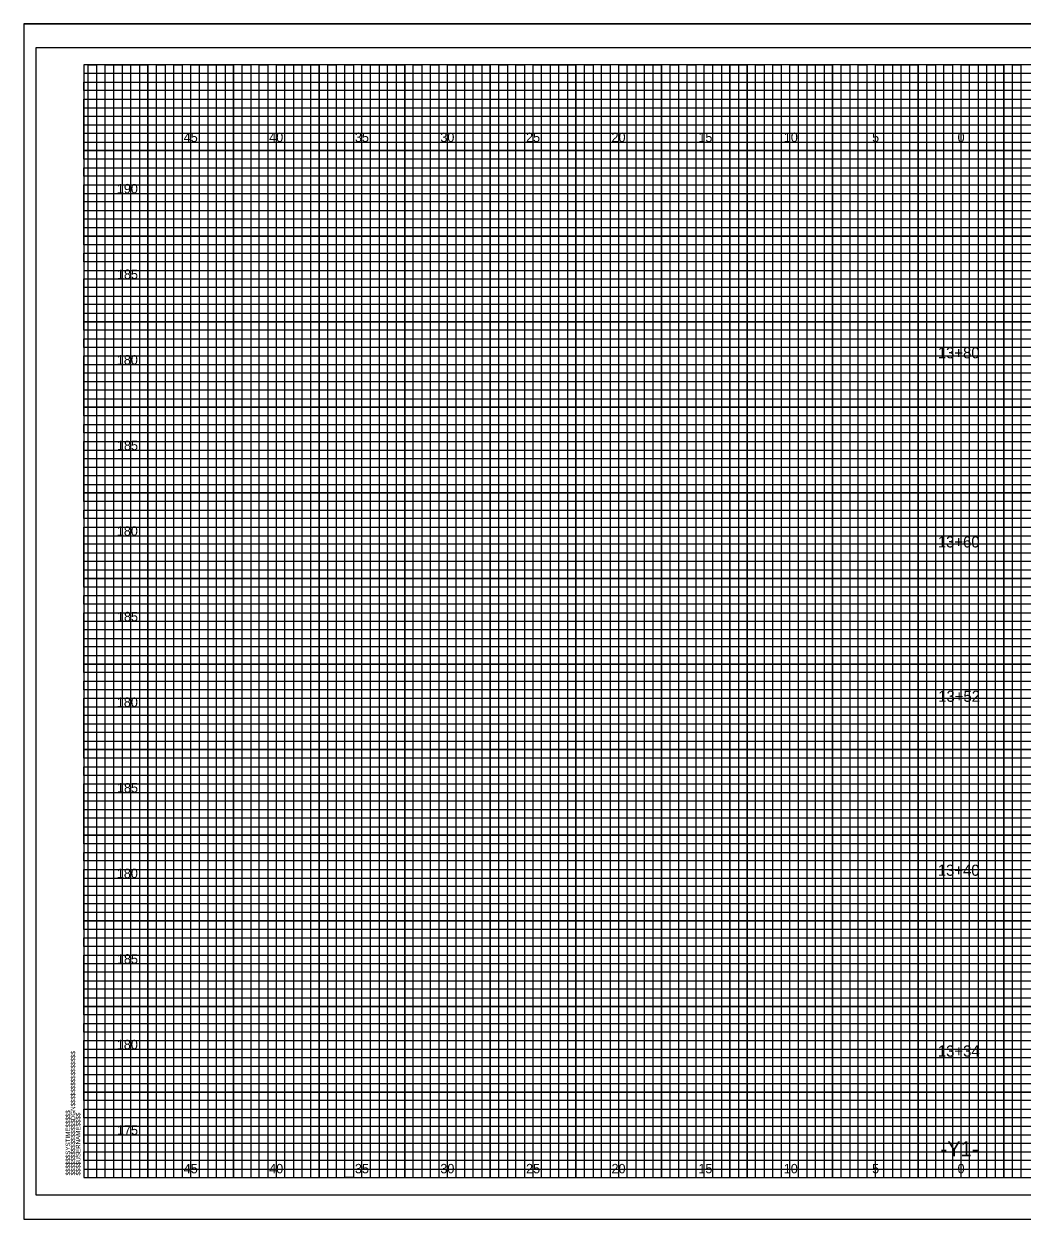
# Model space of a CAD drawing. Extents: x -4 to 103, y -2 to 209.
# Drawn here: x -3.5 to 54.8, y 139.2 to 209.1 of the extents above; entities that cross this region are included whole.
import ezdxf

# ---------------------------------------------------------------- set-up
doc = ezdxf.new("R2010")
doc.units = 0
for name, color, linetype in [('Old_Level_10', 7, 'Continuous'), ('Old_Level_16', 7, 'Continuous'), ('Old_Level_3', 7, 'Continuous'), ('Old_Level_4', 7, 'Continuous'), ('Old_Level_5', 7, 'Continuous'), ('Old_Level_6', 7, 'Continuous'), ('Old_Level_8', 7, 'Continuous'), ('Prop Dimension', 7, 'Continuous'), ('Prop XS Dump Level', 7, 'Continuous'), ('Prop XS Finish Grade Pavement', 7, 'Continuous'), ('Prop XS Subgrade Earthwork', 7, 'Continuous')]:
    doc.layers.add(name, color=color, linetype=linetype)

msp = doc.modelspace()

# ---------------------------------------------------------------- linework, layer by layer
at = {"layer": 'Old_Level_10'}
for p, q in [((1.25, 141.65), (1.25, 206.65)), ((3.75, 141.65), (3.75, 206.65)), ((6.25, 141.65), (6.25, 206.65)), ((8.75, 141.65), (8.75, 206.65)), ((11.25, 141.65), (11.25, 206.65)), ((13.75, 141.65), (13.75, 206.65)), ((16.25, 141.65), (16.25, 206.65)), ((18.75, 141.65), (18.75, 206.65)), ((21.25, 141.65), (21.25, 206.65)), ((23.75, 141.65), (23.75, 206.65)), ((26.25, 141.65), (26.25, 206.65)), ((28.75, 141.65), (28.75, 206.65)), ((31.25, 141.65), (31.25, 206.65)), ((33.75, 141.65), (33.75, 206.65)), ((36.25, 141.65), (36.25, 206.65)), ((38.75, 141.65), (38.75, 206.65)), ((41.25, 141.65), (41.25, 206.65)), ((43.75, 141.65), (43.75, 206.65)), ((46.25, 141.65), (46.25, 206.65)), ((48.75, 141.65), (48.75, 206.65)), ((51.25, 141.65), (51.25, 206.65)), ((53.75, 141.65), (53.75, 206.65)), ((0, 204.15), (74.25, 204.15)), ((0, 201.65), (102.5, 201.65)), ((0, 199.15), (102.5, 199.15)), ((0, 196.65), (102.5, 196.65)), ((0, 194.15), (102.5, 194.15)), ((0, 191.65), (102.5, 191.65)), ((0, 189.15), (102.5, 189.15)), ((0, 186.65), (102.5, 186.65)), ((0, 184.15), (102.5, 184.15)), ((0, 181.65), (102.5, 181.65)), ((0, 179.15), (102.5, 179.15)), ((0, 176.65), (102.5, 176.65)), ((0, 174.15), (102.5, 174.15)), ((0, 171.65), (102.5, 171.65)), ((0, 169.15), (102.5, 169.15)), ((0, 166.65), (102.5, 166.65)), ((0, 164.15), (102.5, 164.15)), ((0, 161.65), (102.5, 161.65)), ((0, 159.15), (102.5, 159.15)), ((0, 156.65), (102.5, 156.65)), ((0, 154.15), (102.5, 154.15)), ((0, 151.65), (102.5, 151.65)), ((0, 149.15), (102.5, 149.15)), ((0, 146.65), (102.5, 146.65)), ((0, 144.15), (102.5, 144.15))]:
    msp.add_line(p, q, dxfattribs=at)
at = {"layer": 'Old_Level_3'}
for p, q in [((-3.5, 209.05), (103.4, 209.05)), ((-3.5, 209.05), (-3.5, 139.225)), ((-3.5, 139.225), (103.4, 139.225))]:
    msp.add_line(p, q, dxfattribs=at)
at = {"layer": 'Old_Level_4'}
msp.add_lwpolyline([(103, 207.65), (-2.8, 207.65), (-2.8, 140.65), (103, 140.65)], close=True, dxfattribs=at)
at = {"layer": 'Old_Level_5'}
msp.add_lwpolyline([(103.4, 209.05), (-3.5, 209.05), (-3.5, 139.225), (103.4, 139.225)], close=True, dxfattribs=at)
at = {"layer": 'Old_Level_6'}
msp.add_lwpolyline([(102.5, 206.65), (0, 206.65), (0, 141.65), (102.5, 141.65)], close=True, dxfattribs=at)
at = {"layer": 'Old_Level_8'}
for points in [[(1.25, 141.65), (1.25, 206.65), (3.75, 206.65), (3.75, 141.65), (6.25, 141.65), (6.25, 206.65), (8.75, 206.65), (8.75, 141.65), (11.25, 141.65), (11.25, 206.65), (13.75, 206.65), (13.75, 141.65), (16.25, 141.65), (16.25, 206.65), (18.75, 206.65), (18.75, 141.65), (21.25, 141.65), (21.25, 206.65), (23.75, 206.65), (23.75, 141.65), (26.25, 141.65), (26.25, 206.65), (28.75, 206.65), (28.75, 141.65), (31.25, 141.65), (31.25, 206.65), (33.75, 206.65), (33.75, 141.65), (36.25, 141.65), (36.25, 206.65), (38.75, 206.65), (38.75, 141.65), (41.25, 141.65), (41.25, 206.65), (43.75, 206.65), (43.75, 141.65), (46.25, 141.65), (46.25, 206.65), (48.75, 206.65), (48.75, 141.65), (51.25, 141.65), (51.25, 206.65), (53.75, 206.65), (53.75, 141.65)], [(102.5, 201.65), (0, 201.65), (0, 204.15), (74.25, 204.15)], [(102.5, 196.65), (0, 196.65), (0, 199.15), (102.5, 199.15)], [(102.5, 191.65), (0, 191.65), (0, 194.15), (102.5, 194.15)], [(102.5, 186.65), (0, 186.65), (0, 189.15), (102.5, 189.15)], [(102.5, 181.65), (0, 181.65), (0, 184.15), (102.5, 184.15)], [(102.5, 176.65), (0, 176.65), (0, 179.15), (102.5, 179.15)], [(102.5, 171.65), (0, 171.65), (0, 174.15), (102.5, 174.15)], [(102.5, 166.65), (0, 166.65), (0, 169.15), (102.5, 169.15)], [(102.5, 161.65), (0, 161.65), (0, 164.15), (102.5, 164.15)], [(102.5, 156.65), (0, 156.65), (0, 159.15), (102.5, 159.15)], [(102.5, 151.65), (0, 151.65), (0, 154.15), (102.5, 154.15)], [(102.5, 146.65), (0, 146.65), (0, 149.15), (102.5, 149.15)], [(0, 144.15), (102.5, 144.15)]]:
    msp.add_lwpolyline(points, dxfattribs=at)
at = {"layer": 'Prop Dimension'}
for points in [[(0, 203.65), (0, 204.65), (74.25, 204.65), (74.25, 205.15), (0, 205.15), (0, 205.65), (74.25, 205.65), (74.25, 206.15), (0, 206.15)], [(0.25, 141.65), (0.25, 206.65), (0.75, 206.65), (0.75, 141.65), (1.75, 141.65), (1.75, 206.65), (2.25, 206.65), (2.25, 141.65), (2.75, 141.65), (2.75, 206.65), (3.25, 206.65), (3.25, 141.65), (4.25, 141.65), (4.25, 206.65), (4.75, 206.65), (4.75, 141.65), (5.25, 141.65), (5.25, 206.65), (5.75, 206.65), (5.75, 141.65), (6.75, 141.65), (6.75, 206.65), (7.25, 206.65), (7.25, 141.65), (7.75, 141.65), (7.75, 206.65), (8.25, 206.65), (8.25, 141.65), (9.25, 141.65), (9.25, 206.65), (9.75, 206.65), (9.75, 141.65), (10.25, 141.65), (10.25, 206.65), (10.75, 206.65), (10.75, 141.65), (11.75, 141.65), (11.75, 206.65), (12.25, 206.65), (12.25, 141.65), (12.75, 141.65), (12.75, 206.65), (13.25, 206.65), (13.25, 141.65), (14.25, 141.65), (14.25, 206.65), (14.75, 206.65), (14.75, 141.65), (15.75, 141.65), (15.25, 141.65), (15.25, 206.65), (15.75, 206.65), (15.75, 141.65), (16.75, 141.65), (16.75, 206.65), (17.25, 206.65), (17.25, 141.65), (17.75, 141.65), (17.75, 206.65), (18.25, 206.65), (18.25, 141.65), (19.25, 141.65), (19.25, 206.65), (19.75, 206.65), (19.75, 141.65), (20.25, 141.65), (20.25, 206.65), (20.75, 206.65), (20.75, 141.65), (21.75, 141.65), (21.75, 206.65), (22.25, 206.65), (22.25, 141.65), (22.75, 141.65), (22.75, 206.65), (23.25, 206.65), (23.25, 141.65), (24.25, 141.65), (24.25, 206.65), (24.75, 206.65), (24.75, 141.65), (25.25, 141.65), (25.25, 206.65), (25.75, 206.65), (25.75, 141.65), (26.75, 141.65), (26.75, 206.65), (27.25, 206.65), (27.25, 141.65), (27.75, 141.65), (27.75, 206.65), (28.25, 206.65), (28.25, 141.65), (29.25, 141.65), (29.25, 206.65), (29.75, 206.65), (29.75, 141.65), (30.25, 141.65), (30.25, 206.65), (30.75, 206.65), (30.75, 141.65)], [(30.75, 141.65), (31.75, 141.65), (31.75, 206.65), (32.25, 206.65), (32.25, 141.65), (32.75, 141.65), (32.75, 206.65), (33.25, 206.65), (33.25, 141.65), (34.25, 141.65), (34.25, 206.65), (34.75, 206.65), (34.75, 141.65), (35.25, 141.65), (35.25, 206.65), (35.75, 206.65), (35.75, 141.65), (36.75, 141.65), (36.75, 206.65), (37.25, 206.65), (37.25, 141.65), (37.75, 141.65), (37.75, 206.65), (37.75, 141.65)], [(38.25, 206.65), (38.25, 141.65), (39.25, 141.65), (39.25, 206.65), (39.75, 206.65), (39.75, 141.65), (40.25, 141.65), (40.25, 206.65), (40.75, 206.65), (40.75, 141.65), (41.75, 141.65), (41.75, 206.65), (42.25, 206.65), (42.25, 141.65), (42.75, 141.65), (42.75, 206.65), (43.25, 206.65), (43.25, 141.65), (43.75, 141.65), (44.25, 141.65), (44.25, 206.65), (44.75, 206.65), (44.75, 141.65), (45.25, 141.65), (45.25, 206.65), (45.75, 206.65), (45.75, 141.65), (46.75, 141.65), (46.75, 206.65), (47.25, 206.65), (47.25, 141.65), (47.75, 141.65), (47.75, 206.65), (48.25, 206.65), (48.25, 141.65), (49.25, 141.65), (49.25, 206.65), (49.75, 206.65), (49.75, 141.65), (50.25, 141.65), (50.25, 206.65), (50.75, 206.65), (50.75, 141.65), (51.75, 141.65), (51.75, 206.65), (52.25, 206.65), (52.25, 141.65), (52.75, 141.65), (52.75, 206.65), (53.25, 206.65), (53.25, 141.65), (54.25, 141.65), (54.25, 206.65), (54.75, 206.65), (54.75, 141.65), (55.25, 141.65)], [(102.5, 203.65), (0, 203.65)], [(102.5, 202.65), (0, 202.65), (0, 203.15), (102.5, 203.15)], [(102.5, 201.15), (0, 201.15), (0, 202.15), (102.5, 202.15)], [(102.5, 200.15), (0, 200.15), (0, 200.65), (102.5, 200.65)], [(102.5, 198.65), (0, 198.65), (0, 199.65), (102.5, 199.65)], [(102.5, 197.65), (0, 197.65), (0, 198.15), (102.5, 198.15)], [(102.5, 196.15), (0, 196.15), (0, 197.15), (102.5, 197.15)], [(102.5, 195.15), (0, 195.15), (0, 195.65), (102.5, 195.65)], [(0, 194.65), (102.5, 194.65)], [(102.5, 193.65), (0, 193.65)], [(102.5, 192.65), (0, 192.65), (0, 193.15), (102.5, 193.15)], [(102.5, 191.15), (0, 191.15), (0, 192.15), (102.5, 192.15)], [(102.5, 190.15), (0, 190.15), (0, 190.65), (102.5, 190.65)], [(102.5, 188.65), (0, 188.65), (0, 189.65), (102.5, 189.65)], [(102.5, 187.65), (0, 187.65), (0, 188.15), (102.5, 188.15)], [(102.5, 186.15), (0, 186.15), (0, 187.15), (102.5, 187.15)], [(102.5, 185.15), (0, 185.15), (0, 185.65), (102.5, 185.65)], [(102.5, 183.65), (0, 183.65), (0, 184.65), (102.5, 184.65)], [(102.5, 182.65), (0, 182.65), (0, 183.15), (102.5, 183.15)], [(102.5, 181.15), (0, 181.15), (0, 182.15), (102.5, 182.15)], [(102.5, 180.15), (0, 180.15), (0, 180.65), (102.5, 180.65)], [(102.5, 178.65), (0, 178.65), (0, 179.65), (102.5, 179.65)], [(102.5, 177.65), (0, 177.65), (0, 178.15), (102.5, 178.15)], [(102.5, 176.15), (0, 176.15), (0, 177.15), (102.5, 177.15)], [(102.5, 175.15), (0, 175.15), (0, 175.65), (102.5, 175.65)], [(102.5, 173.65), (0, 173.65), (0, 174.65), (102.5, 174.65)], [(102.5, 172.65), (0, 172.65), (0, 173.15)], [(0, 173.15), (102.5, 173.15)], [(102.5, 171.15), (0, 171.15), (0, 172.15), (102.5, 172.15)], [(102.5, 170.15), (0, 170.15), (0, 170.65), (102.5, 170.65)], [(102.5, 168.65), (0, 168.65), (0, 169.65), (102.5, 169.65)], [(102.5, 167.65), (0, 167.65), (0, 168.15), (102.5, 168.15)], [(102.5, 166.15), (0, 166.15), (0, 167.15), (102.5, 167.15)], [(102.5, 165.15), (0, 165.15), (0, 165.65), (102.5, 165.65)], [(102.5, 163.65), (0, 163.65), (0, 164.65), (102.5, 164.65)], [(102.5, 162.65), (0, 162.65), (0, 163.15), (102.5, 163.15)], [(102.5, 161.15), (0, 161.15), (0, 162.15), (102.5, 162.15)], [(102.5, 160.15), (0, 160.15), (0, 160.65), (102.5, 160.65)], [(102.5, 158.65), (0, 158.65), (0, 159.65), (102.5, 159.65)], [(102.5, 157.65), (0, 157.65), (0, 158.15), (102.5, 158.15)], [(102.5, 156.15), (0, 156.15), (0, 157.15), (102.5, 157.15)], [(102.5, 155.15), (0, 155.15), (0, 155.65), (102.5, 155.65)], [(102.5, 153.65), (0, 153.65), (0, 154.65), (102.5, 154.65)], [(102.5, 152.65), (0, 152.65), (0, 153.15), (102.5, 153.15)], [(102.5, 151.15), (0, 151.15), (0, 152.15), (102.5, 152.15)], [(102.5, 150.15), (0, 150.15), (0, 150.65), (102.5, 150.65)], [(102.5, 148.65), (0, 148.65), (0, 149.65), (102.5, 149.65)], [(102.5, 147.65), (0, 147.65), (0, 148.15), (102.5, 148.15)], [(102.5, 146.15), (0, 146.15), (0, 147.15), (102.5, 147.15)], [(102.5, 145.15), (0, 145.15), (0, 145.65), (102.5, 145.65)], [(102.5, 143.65), (0, 143.65), (0, 144.65), (102.5, 144.65)], [(102.5, 142.65), (0, 142.65), (0, 143.15), (102.5, 143.15)], [(0, 142.15), (102.5, 142.15)]]:
    msp.add_lwpolyline(points, dxfattribs=at)

# ---------------------------------------------------------------- texts
at = {"layer": 'Old_Level_16'}
for s, p in [('45', (5.8399, 202.15)), ('40', (10.8313, 202.15)), ('35', (15.8399, 202.15)), ('30', (20.8313, 202.15)), ('25', (25.8399, 202.15)), ('20', (30.8313, 202.15)), ('15', (35.9058, 202.15)), ('10', (40.8971, 202.15)), ('5', (46.0574, 202.15)), ('0', (51.0488, 202.15)), ('0', (51.0488, 202.15)), ('45', (5.8399, 141.9)), ('40', (10.8313, 141.9)), ('35', (15.8399, 141.9)), ('30', (20.8313, 141.9)), ('25', (25.8399, 141.9)), ('20', (30.8313, 141.9)), ('15', (35.9058, 141.9)), ('10', (40.8971, 141.9)), ('5', (46.0574, 141.9)), ('0', (51.0488, 141.9)), ('0', (51.0488, 141.9))]:
    msp.add_text(s, height=0.55, dxfattribs=at).set_placement(p)
at = {"layer": 'Old_Level_6'}
for s, p in [('$$$$$$$$$$$$$$$$DGN$$$$$$$$$$$$$$$$', (-0.5, 141.775)), ('$$$$$$SYSTIME$$$$$', (-0.7973, 141.7747)), ('$$$$USERNAME$$$$', (-0.2, 141.775))]:
    msp.add_text(s, height=0.2625, rotation=90, dxfattribs=at).set_placement(p)
at = {"layer": 'Old_Level_8'}
msp.add_text('040397', height=0.0025, rotation=90, dxfattribs=at).set_placement((-0.0007, 206.6364))
at = {"layer": 'Prop XS Dump Level'}
msp.add_text('-Y1-', height=0.875, dxfattribs=at).set_placement((50.0581, 142.9))
at = {"layer": 'Prop XS Finish Grade Pavement'}
for s, p in [('13+80', (49.8934, 189.5136)), ('13+60', (49.8934, 178.464)), ('13+52', (49.9186, 169.4447)), ('13+40', (49.8934, 159.2816)), ('13+34', (49.8976, 148.7182))]:
    msp.add_text(s, height=0.65, dxfattribs=at).set_placement(p)
at = {"layer": 'Prop XS Subgrade Earthwork'}
for s, p in [('190', (1.9296, 199.15)), ('185', (1.9383, 194.15)), ('180', (1.9296, 189.15)), ('185', (1.9383, 184.15)), ('180', (1.9296, 179.15)), ('185', (1.9383, 174.15)), ('180', (1.9296, 169.15)), ('185', (1.9383, 164.15)), ('180', (1.9296, 159.15)), ('185', (1.9383, 154.15)), ('180', (1.9296, 149.15)), ('175', (1.9383, 144.15))]:
    msp.add_text(s, height=0.55, dxfattribs=at).set_placement(p)

doc.saveas('drawing.dxf')
